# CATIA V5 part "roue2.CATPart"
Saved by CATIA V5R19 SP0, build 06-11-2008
Part number: roue2
Bounding box of the stored display mesh (mm): x -780 to -220, y -10 to 550, z -45 to 30
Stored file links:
  C:\Users\Thibaud\Desktop\IFMA\thinkmotion\IAO\modele_catia\roue2.CATPart
  C:\Users\Thibaud\Desktop\IFMA\thinkmotion\IAO\modele_catia\roue1.CATPart
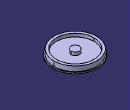
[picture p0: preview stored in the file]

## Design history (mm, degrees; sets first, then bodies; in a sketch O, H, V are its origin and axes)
Body1 (main body)
  Plane1: stored without definition
  Line1 "lineaire_rect_roue2_sabot2": stored without definition
  Circle1 "contour_roue2": stored without definition
  Sketch1 on Plane1, origin (0, 0, 0), H (1, 0, 0), V (0, 1, 0)
    circle A1 centre (-500, 270) radius 266.8333
    reference projected point E1 (-240, 330) from Line1
    reference projected circle E2 centre (-500, 270) radius 266.8333 from Circle1
    coincidence: A1 E1
    concentricity: A1 E2
  Pad1: profile Sketch1, direction (0, 0, 1), length 30, mirrored extent
  Circle2 "contour_roue2": stored without definition
  Line2 "axe_pivot_roue2_batit": stored without definition
  Sketch2 on start face of Pad1, origin (0, 0, -30), H (1, 0, 0), V (0, -1, 0)
    circle A1 centre (-500, -270) radius 280
    point P1 (-500, -270)
    reference projected point E1 (-500, -270) from Line2
    radius A1 = 280
    coincidence: P1 E1
  Pad2: profile Sketch2, direction (0, 0, -1), length 15
  Line3 "axe_pivot_roue2_batit": stored without definition
  Line4 "axe_pivot_roue2_batit": stored without definition
  Sketch3 on end face of Pad1, origin (0, 0, 30), H (1, 0, 0), V (0, 1, 0)
    circle A1 centre (-500, 270) radius 235
    point P1 (-500, 270)
    reference projected point E1 (-500, 270) from Line3
    circle A2 centre (-500, 270) radius 52.5
    point P2 (-500, 270)
    reference projected point E2 (-500, 270) from Line4
    radius A1 = 235
    radius A2 = 52.5
    coincidence: P1 E1, P2 E2
  Pocket1: profile Sketch3, direction (0, 0, -1), length 40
